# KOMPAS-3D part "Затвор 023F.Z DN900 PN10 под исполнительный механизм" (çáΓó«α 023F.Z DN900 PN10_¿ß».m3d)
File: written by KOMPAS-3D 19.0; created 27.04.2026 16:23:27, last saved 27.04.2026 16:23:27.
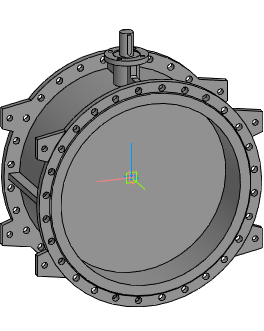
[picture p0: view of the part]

Document properties: Автор: Евгений; Полное имя файла: Z:\3.Личные\kachalov\3d для проектировщиков\1.7 Тип 023F.Z Затвор дисковый поворотный фланцевый с двумя эксцентриками\Затвор 023F.Z DN200-DN1600_исп\_stp_Затвор 023F.Z DN200-DN1600_исп\Затвор 023F.Z DN900 PN10_исп.m3d

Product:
- Part/product: Затвор 023F.Z DN900 PN10 под исполнительный механизм

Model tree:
1. Операция без истории:1  (labels: Затвор 023F.Z DN900 PN10 под исполнительный механизм)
